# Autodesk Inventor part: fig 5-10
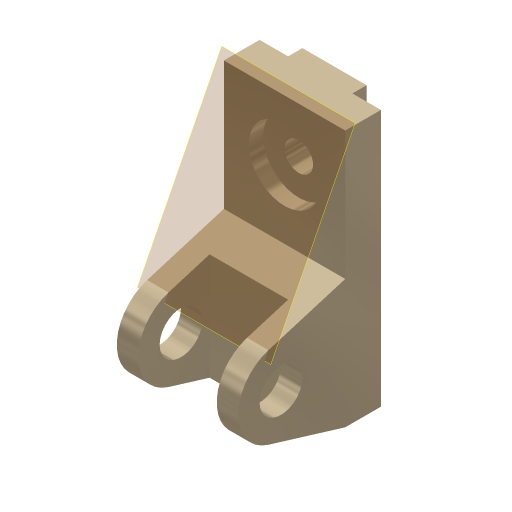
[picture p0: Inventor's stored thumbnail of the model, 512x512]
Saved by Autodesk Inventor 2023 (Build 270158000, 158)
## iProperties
Created: 2001-11
Part Number: fig 5-10
Document SubType Name: Modeling
Designer: Renu Muthoo
Density: 1 g/cm^3
Material: Generic
Appearance: Metal-Titanium (Polished)
Control State: 0
Master: False
Checked Out: False
Shininess: 65.0
Angle Display Precision: 2
Document Length Units: 11269
Document Angle Units: 11279
Document Time Units: 11290
Document Mass Units: 11283
Document Length Units Precision: 3
Document Angle Units Precision: 2
Compacted: False
Density: 0.0
Volumn: 0.0
Area: 0.0
PropertySet Name: Model Information
Author: Renu Muthoo
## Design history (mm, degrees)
node "Sketch1"
sketch "Sketch2"
  geometry: L1 (33.257, 104.664)-(33.257, -75.336); L2 (33.257, -75.336)-(8.257, -75.336); L3 (8.257, -75.336)-(-45.451, -59.045); L4 (-45.451, -1.628)-(8.257, 14.664); L5 (8.257, 14.664)-(8.257, 104.664); L6 (8.257, 104.664)-(33.257, 104.664); C1 r 15 at (-36.743, -30.336); A1 r 30 centre (-36.743, -30.336) between (-45.451, -1.628) and (-45.451, -59.045)
  constraints: 12 end point, 2 centre point, 2 equal length, 2 parallel, 2 point on circle, 2 tangent, 1 coincident, 1 perpendicular, 1 vertical
  dimensions: "d0" = 180 distance of L1.start L1.end; "d1" = 30 radius of A1; "d2" = 25 distance of L5.end L1.start; "d3" = 45 distance from line of L2 A1.centre; "d4" = 70 distance from line of L1 A1.centre; "d5" = 30 diameter of C1
extrude "Extrusion1" new body sketch "Sketch2" distance "d6" = 85; taper "d7" = 0 deg
workplane "Work Plane1"
sketch "Sketch3"
  geometry: L1 (15, 62.364)-(70, 62.364); L2 (70, 62.364)-(70, -52.386); L3 (70, -52.386)-(15, -52.386); L4 (15, -52.386)-(15, 62.364); L5 (0, -45)-(0, -28.708) reference
  constraints: 8 end point, 2 parallel, 1 horizontal, 1 perpendicular
  dimensions: "d8" = 55 distance of L1.start L1.end; "d9" = 15 distance between parallel lines of L5 L4
extrude "Extrusion2" cut sketch "Sketch3" distance "d10" = 50; taper "d11" = 0 deg
sketch "Sketch4"
  geometry: L1 (0, 25)-(85, 25) reference; L2 (0, 0)-(0, 25) reference; L3 (20, 25)-(65, 25); L4 (65, 25)-(65, 35); L5 (65, 35)-(20, 35); L6 (20, 35)-(20, 25)
  constraints: 8 end point, 2 parallel, 1 horizontal, 1 perpendicular, 1 point on line
  dimensions: "d12" = 45 distance of L4.end L5.end; "d13" = 10 distance of L3.end L4.end; "d14" = 20 distance between parallel lines of L2 L6
extrude "Extrusion3" join sketch "Sketch4" stored distance "d15" = 50; taper "d16" = 0 deg
sketch "Sketch5"
  geometry: L1 (85, 0)-(85, 90) reference; L2 (0, 90)-(85, 90) reference; 1 further point
  dimensions: "d17" = 42 distance from line of L2 point (42.5, 48); "d18" = 42.5 distance from line of L1 point (42.5, 48)
hole "Hole1" sketch "Sketch5" at (42.5, 48) diameter "d19" = 20; stored, may be unused: countersink angle "d23" = 82 deg, drill point angle "d25" = 118 deg; dims "d20" = 6, "d21" = 50, "d22" = 10, "d24" = 8
workplane "Work Plane4"
body "Solid1"
